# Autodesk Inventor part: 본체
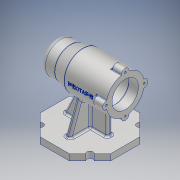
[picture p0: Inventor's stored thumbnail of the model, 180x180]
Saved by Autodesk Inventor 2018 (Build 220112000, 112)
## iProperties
Created: 2019-12
Part Number: 본체
Material: 알루미늄 6061
Document SubType Name: Modeling
Designer: USER
Density: 2.7 g/cm^3
Appearance: 알루미늄 - 평지
Mass: 726.203 g
Surface Area: 715.726 cm^2
Volume: 268.964 cm^3
Author: USER
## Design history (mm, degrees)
sketch "스케치1"
  geometry: L1 (0, 0)-(132.064, 0); L2 (0, 0)-(0, 25); L3 (0, 25)-(25, 25); L4 (25, 25)-(45, 30); L5 (45, 30)-(112, 30); L6 (112, 30)-(112, 21); L7 (97, 21)-(97, 21); L8 (94, 24)-(46, 24); L9 (43, 21)-(43, 21); L10 (43, 21)-(31, 21); L11 (31, 21)-(31, 17.5); L12 (31, 17.5)-(13, 17.5); L13 (13, 17.5)-(13, 16); L14 (13, 16)-(9, 16); L15 (9, 16)-(9, 10.5); L16 (9, 10.5)-(9, 10.5); L17 (6, 7.5)-(6, 0); L18 (97, 21)-(112, 21); L19 (0, 0)-(6, 0); A1 r 3 centre (9, 7.5) between (9, 10.5) and (6, 7.5); A2 r 3 centre (46, 21) between (46, 24) and (43, 21); A3 r 3 centre (94, 21) between (97, 21) and (94, 24)
  constraints: 38 end point, 12 perpendicular, 6 point on circle, 6 tangent, 3 centre point, 2 equal radius, 2 horizontal, 2 vertical, 1 collinear, 1 parallel
  dimensions: "d0" = 25 distance of L1.start L2.end; "d1" = 25 distance of L2.end L3.end; "d4" = 112 distance between parallel lines of L2 L6; "d5" = 30 distance between parallel lines of L1 L5; "d7" = 15 distance of L6.end L7.start; "d8" = 21 distance between parallel lines of L1 L18; "d9" = 24 distance between parallel lines of L1 L8; "d15" = 16 distance between parallel lines of L1 L14; "d20" = 17.5 distance between parallel lines of L1 L12; "d21" = 21 distance between parallel lines of L1 L10; "d97" = 54 distance of L7.start L9.end; "d98" = 45 distance from line of L2 L4.end; "d101" = 12 distance from line of L9.start L11; "d102" = 18 distance from line of L11.end L13; "d103" = 4 distance from line of L13.end L15; "d104" = 6 distance between parallel lines of L2 L17; "d106" = 9 distance from line of L2 A1.centre (derived); "d107" = 3 radius of A2; "d108" = 10.5 distance from line of L1 L15.end
revolve "회전2" sketch "스케치1" stored, may be unused: angle "d22" = 90 deg
sketch "스케치3"
  geometry: L1 (0, 0)-(0, 57.725); L2 (0, 0)-(-52.854, 0); C1 r 30 at (0, 0); C2 r 6 at (-30, 0); 2 further points
  constraints: 4 end point, 2 centre point, 1 coincident, 1 horizontal, 1 horizontal alignment, 1 point on line, 1 vertical, 1 other
  dimensions: "d23" = 60 diameter of C1; "d24" = 12 diameter of C2
extrude "돌출1" join sketch "스케치3" distance "d25" = 16; taper "d26" = 0 deg
sketch "스케치4"
  geometry: A1 r 6 centre (0, 0) between (0.6, 5.97) and (0.6, -5.97) reference; 2 further points
  constraints: 1 coincident
hole "구멍1" sketch "스케치4" at (0, 0) diameter "d27" = 3.242; stored, may be unused: countersink angle "d31" = 90 deg, drill point angle "d33" = 118 deg; dims "d28" = 8, "d29" = 4, "d30" = 2, "d32" = 11
node "작업 평면1"
sketch "스케치5"
  geometry: L1 (0, 0)-(112, 0); L2 (0, 0)-(0, 112); L3 (56, 64.671)-(56, 0); L4 (0, 23.196)-(32.804, 56); L5 (32.804, 56)-(79.196, 56); L6 (79.196, 56)-(112, 23.196); L7 (112, 23.196)-(112, -23.196); L8 (112, -23.196)-(79.196, -56); L9 (79.196, -56)-(32.804, -56); L10 (32.804, -56)-(0, -23.196); L11 (0, -23.196)-(0, 23.196); 1 further point
  constraints: 22 end point, 1 coincident, 1 horizontal, 1 point on line, 1 vertical, 17 other
  dimensions: "d38" = 112 distance of L1.start L1.end; "d39" = 112 distance of L1.start L2.end; "d40" = 56 distance between parallel lines of L2 L3; "d41" = 180 deg angle of L2 L11; "d42" = 0 distance from line of L1 L3.end
extrude "돌출2" join sketch "스케치5" distance "d43" = 10; taper "d44" = 0 deg
sketch "스케치6"
  geometry: L1 (0, 0)-(56, 0); L2 (56, 0)-(95.598, 39.598); L3 (79.196, 56)-(112, 23.196) reference; L4 (56, 0)-(112, 0); C1 r 56 at (56, 0); C2 r 5 at (95.598, 39.598); C3 r 5 at (16.402, 39.598); C4 r 5 at (16.402, -39.598); C5 r 5 at (95.598, -39.598)
  constraints: 6 end point, 5 centre point, 2 coincident, 2 horizontal, 1 equal length, 1 midpoint, 9 other
  dimensions: "d45" = 56 distance of L1.start L1.end; "d46" = 112 diameter of C1; "d47" = 45 deg angle of L4 L2 (derived); "d48" = 10 diameter of C2; "d53" = 360 deg dimension on L2.start C2.centre (derived)
extrude "돌출4" cut sketch "스케치6" distance "d55" = 10; taper "d56" = 0 deg
fillet "모깎기1" dims "d57" = 0.3
sketch "스케치7"
  geometry: L1 (0, 0)-(150.369, 0); L2 (0, 0)-(0, 79.943); L3 (56, 76.136)-(56, -74.333); L4 (18, -3.594)-(87, -3.594); L5 (87, -3.594)-(87, 4.406); L6 (87, 4.406)-(18, 4.406); L7 (18, 4.406)-(18, -3.594); L8 (87, -3.594)-(18, 4.406); L9 (112, 23.196)-(112, -23.196) reference; L10 (32.804, 56)-(79.196, 56) reference; 2 further points
  constraints: 16 end point, 3 point on line, 2 horizontal, 2 parallel, 2 vertical, 1 midpoint, 1 perpendicular
  dimensions: "d58" = 56 distance between parallel lines of L2 L3; "d59" = 8 distance of L5.end L4.end; "d61" = 18 distance between parallel lines of L2 L7; "d62" = 25 distance between parallel lines of L9 L5
extrude "돌출6" join sketch "스케치7" distance "d68" = 45; taper "d69" = 0 deg
feature "면 기울기1" dims angle "d70" = 25 deg
sketch "스케치8"
  geometry: L1 (0, 0)-(56, 0); L2 (60, 36)-(52, 36); L3 (52, 36)-(52, -36); L4 (52, -36)-(60, -36); L5 (60, -36)-(60, 36); L6 (60, 36)-(52, -36); L7 (52, 36)-(60, -36)
  constraints: 14 end point, 2 horizontal, 2 midpoint, 2 parallel, 1 perpendicular
  dimensions: "d71" = 56 distance of L1.start L1.end; "d72" = 8 distance of L4.end L3.end; "d73" = 72 distance of L3.end L2.end
extrude "돌출7" join sketch "스케치8" distance "d74" = 50; taper "d75" = 0 deg
feature "면 기울기2" dims angle "d76" = 20 deg
feature "면 기울기3" dims angle "d77" = 20 deg
sketch "스케치9"
  geometry: C1 r 24 at (0, 0) reference; C2 r 24 at (0, 0); 1 further point
  constraints: 1 centre point, 1 coincident
  dimensions: "d78" = 48 diameter of C2
extrude "돌출8" cut sketch "스케치9" distance "d79" = 10; taper "d80" = 0 deg
fillet "모깎기2" dims "d81" = 1
fillet "모깎기4" dims "d83" = 3
fillet "모깎기5" dims "d84" = 3
fillet "모깎기6" dims "d85" = 2
node "작업 평면3"
sketch "스케치11"
  geometry: L1 (0, 0)-(-136.481, 0); L2 (0, 22)-(0, -22) reference; 1 further point
  constraints: 2 end point, 1 horizontal, 1 other
  dimensions: "d88" = 0 distance from line of L1 point (-71, 0); "d92" = 71 distance from line of L2 point (-71, 0)
feature "엠보싱1" sketch "스케치11" dims "d0" = 25, "d1" = 25, "d4" = 112, "d5" = 30, "d7" = 15, "d8" = 21, "d9" = 24, "d15" = 16, "d20" = 17.5, "d21" = 21, "d90" = 0.5, "d91" = 0, "d97" = 54, "d98" = 45, "d101" = 12, "d102" = 18, "d103" = 4, "d104" = 6, "d106" = 9 (derived), "d107" = 3, "d108" = 10.5
fillet "모깎기7" dims "d93" = 10
fillet "모깎기8" dims "d94" = 3
node "솔리드2"
pattern_circular "원형 패턴1" dims angle "d35" = 360 deg
